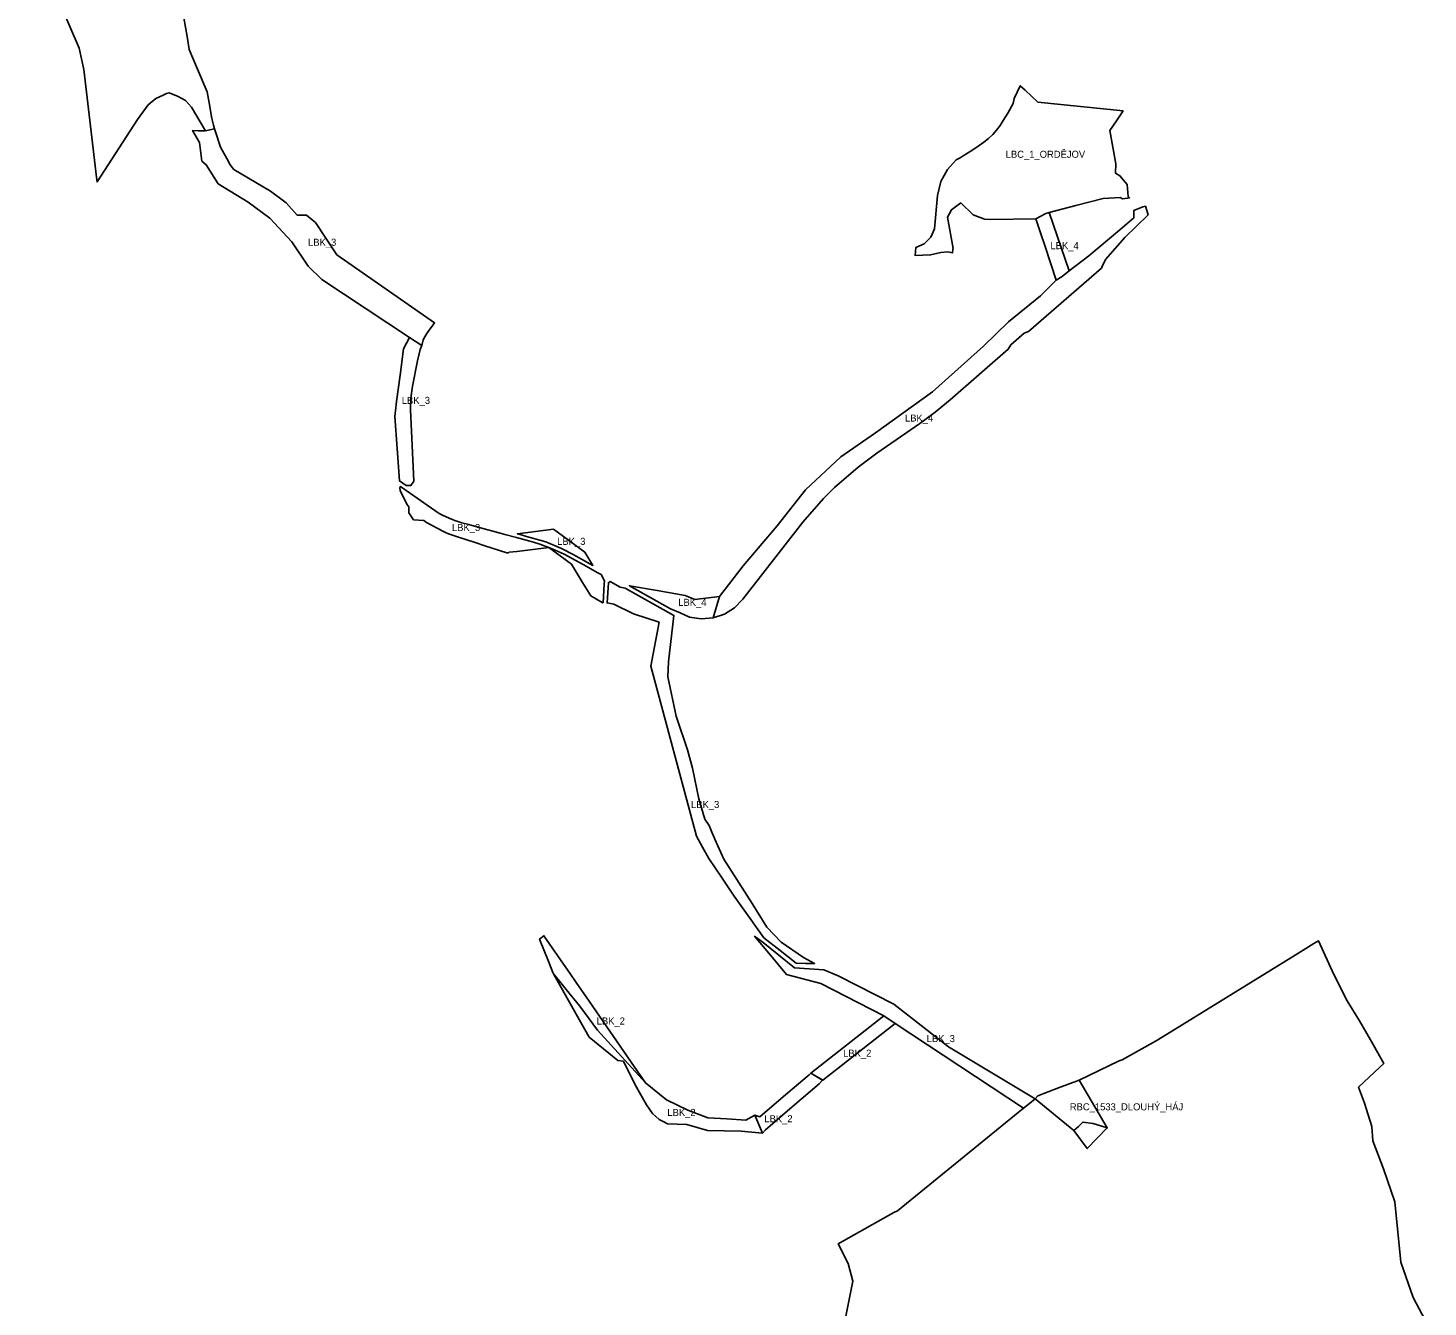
# Model space of a CAD drawing. Extents: x -521939 to -516426, y -1197857 to -1189576.
# Drawn here: x -519448 to -517855, y -1195182 to -1193727 of the extents above; entities that cross this region are included whole.
import ezdxf

# ---------------------------------------------------------------- set-up
doc = ezdxf.new("R2010")
doc.units = 0
for name, color, linetype in [('91250013', 7, 'Continuous'), ('91270013', 7, 'Continuous'), ('91280013', 7, 'Continuous'), ('91280023', 7, 'Continuous')]:
    doc.layers.add(name, color=color, linetype=linetype)

msp = doc.modelspace()

# ---------------------------------------------------------------- linework, layer by layer
at = {"layer": '91250013'}
for points in [[(-517855.27, -1195202.9), (-517872.07, -1195170.61), (-517886.13, -1195130.55), (-517892.85, -1195062.16), (-517905.77, -1195024.59), (-517918.02, -1194992.59), (-517919.16, -1194976.41), (-517927.44, -1194949.61), (-517934.18, -1194931.51), (-517910.02, -1194908.82), (-517905.52, -1194904.59), (-517920.71, -1194877.9), (-517933.13, -1194856.07), (-517947.22, -1194833.42), (-517962.22, -1194803.3), (-517979.82, -1194765.19), (-517984.97, -1194768.36), (-518006.26, -1194781.46), (-518162.69, -1194877.72), (-518167.76, -1194880.84), (-518203.35, -1194900.68), (-518206.51, -1194901.69), (-518252.06, -1194923.56), (-518220.17, -1194977.86), (-518242.88, -1195001.36), (-518257.99, -1194980.81), (-518302.06, -1194944.78)], [(-518302.06, -1194944.78), (-518257.99, -1194980.81), (-518253, -1194976.13), (-518248.01, -1194971.45), (-518236.28, -1194972.79), (-518220.17, -1194977.86), (-518252.06, -1194923.56), (-518275.61, -1194932.46), (-518299.16, -1194941.37), (-518302.06, -1194944.78)], [(-518302.06, -1194944.78), (-518308.71, -1194950.18), (-518315.37, -1194955.58), (-518387.11, -1195013.83), (-518458.85, -1195072.09), (-518462.79, -1195074.28), (-518526.18, -1195109.58), (-518514.93, -1195132.02), (-518509.49, -1195152.1), (-518518.19, -1195195.9)]]:
    msp.add_lwpolyline(points, dxfattribs=at)
at = {"layer": '91270013'}
for points in [[(-519270.68, -1193715.28), (-519266.62, -1193736.71), (-519264.33, -1193751.44), (-519255.98, -1193771.28), (-519244.01, -1193799.73), (-519241.81, -1193812.07), (-519238.75, -1193829.99), (-519237, -1193837.71), (-519235.66, -1193841.81), (-519240.85, -1193842.8), (-519246.03, -1193843.78), (-519261.79, -1193816.98), (-519268.67, -1193809.37), (-519276.88, -1193804.99), (-519287.39, -1193800.73), (-519290.34, -1193801.33), (-519294.27, -1193803.26), (-519302.54, -1193807.3), (-519311.2, -1193814.52), (-519323.09, -1193831.25), (-519369.32, -1193902.04), (-519369.96, -1193896.6), (-519384.42, -1193774.3), (-519389.47, -1193750.04), (-519447.84, -1193614.85)], [(-518301.52, -1193943.97), (-518352.63, -1193944.77), (-518359.82, -1193944.27), (-518372.52, -1193939.49), (-518386.71, -1193925.92), (-518397.26, -1193933.79), (-518401.9, -1193942.24), (-518395.57, -1193977.74), (-518395.64, -1193978.34), (-518396.13, -1193982.66), (-518401.32, -1193981.65), (-518409.46, -1193982.4), (-518421.1, -1193985.13), (-518438.69, -1193985.6), (-518437.85, -1193976.61), (-518428.22, -1193972.32), (-518420.66, -1193964.97), (-518416.55, -1193955.26), (-518413.23, -1193917.44), (-518409.28, -1193901.67), (-518401.76, -1193888.12), (-518391.88, -1193876.83), (-518387.64, -1193874.51), (-518383.89, -1193872.23), (-518374.08, -1193866.27), (-518365.87, -1193860.59), (-518360.35, -1193856.9), (-518355.18, -1193852.77), (-518350.39, -1193848.21), (-518346.01, -1193843.26), (-518342.06, -1193837.96), (-518338.57, -1193832.31), (-518333.17, -1193823.89), (-518327.1, -1193813.04), (-518326.08, -1193807.13), (-518319.09, -1193792.65), (-518313.53, -1193797.88), (-518299.08, -1193811.34), (-518250.59, -1193816.37), (-518202.1, -1193821.4), (-518209.67, -1193832.42), (-518217.23, -1193843.45), (-518210.37, -1193881.64), (-518210.66, -1193892.12), (-518205.81, -1193894.97), (-518197.41, -1193905.18), (-518196.27, -1193918.65), (-518194.69, -1193919.99), (-518195.92, -1193920.22), (-518197.16, -1193920.46), (-518200, -1193920.94), (-518202.84, -1193921.41), (-518205.6, -1193919.97), (-518224.66, -1193920.83), (-518255.82, -1193928.83), (-518286.34, -1193937.02), (-518290.16, -1193938.05), (-518301.52, -1193943.97)]]:
    msp.add_lwpolyline(points, dxfattribs=at)
at = {"layer": '91280013'}
for points in [[(-519013.71, -1194079.07), (-519113.44, -1194013.16), (-519129.07, -1193997.96), (-519147.85, -1193970.15), (-519172.57, -1193943.22), (-519197.38, -1193925.03), (-519231.57, -1193904.08), (-519245.14, -1193882.61), (-519249.93, -1193878.39), (-519252.82, -1193857.23), (-519260.59, -1193843.56), (-519254.04, -1193843.81), (-519247.48, -1193844.06), (-519246.03, -1193843.78), (-519240.85, -1193842.8), (-519235.66, -1193841.81), (-519234.57, -1193845.15), (-519228.9, -1193862.43), (-519221.81, -1193875.3), (-519217.8, -1193882.51), (-519215.12, -1193886.12), (-519213.53, -1193887.89), (-519171.95, -1193912.59), (-519154.26, -1193925.95), (-519141.58, -1193939.77), (-519136.36, -1193939.9), (-519131.15, -1193940.03), (-519124.61, -1193945.28), (-519120.98, -1193948.19), (-519096.71, -1193984.89), (-518985.38, -1194062.49), (-518989.19, -1194067.6), (-518991.71, -1194071.11), (-518994.22, -1194074.61), (-518996.26, -1194078.2), (-518998.31, -1194081.79), (-518999.95, -1194088.17), (-519013.71, -1194079.07)], [(-518301.52, -1193943.97), (-518290.16, -1193938.05), (-518286.34, -1193937.02), (-518263.35, -1194003.2), (-518271.56, -1194009.45), (-518278.37, -1194013.9), (-518290.94, -1193975.36), (-518296.12, -1193959.95), (-518301.52, -1193943.97)], [(-518883.44, -1194304.45), (-518885.16, -1194303.95), (-518891.04, -1194302.25), (-518849.92, -1194297), (-518814.52, -1194323.2), (-518805.31, -1194338.19), (-518827.82, -1194325.64), (-518840.84, -1194318.92), (-518858.91, -1194311.54), (-518883.44, -1194304.45)], [(-518677.75, -1194626.77), (-518673.12, -1194633.99), (-518670.02, -1194641.47), (-518667.28, -1194647.83), (-518666.51, -1194649.62), (-518656.27, -1194672.17), (-518623.89, -1194722.86), (-518607.41, -1194749.43), (-518591.06, -1194766.84), (-518565.58, -1194784.24), (-518553.06, -1194791.06), (-518563.47, -1194790.77), (-518573.88, -1194790.47), (-518592.32, -1194776.2), (-518610.75, -1194761.93), (-518627.58, -1194738.16), (-518644.41, -1194714.39), (-518658.98, -1194692.9), (-518673.54, -1194671.4), (-518680.54, -1194658.74), (-518687.55, -1194646.08), (-518739.33, -1194452.9), (-518729.94, -1194402.91), (-518759.18, -1194393.46), (-518781.58, -1194382.39), (-518789.19, -1194380.84), (-518787.62, -1194357.85), (-518785.49, -1194356.68), (-518774.24, -1194362.95), (-518768.4, -1194363.91), (-518713.15, -1194395.12), (-518719.42, -1194447.81), (-518719.92, -1194464.77), (-518710.33, -1194509.64), (-518697.48, -1194547.94), (-518691.92, -1194568.93), (-518684.82, -1194603.84), (-518677.75, -1194626.77)], [(-518661.16, -1194373.51), (-518668.49, -1194397.81), (-518681.94, -1194398.95), (-518695.28, -1194396.89), (-518705.84, -1194392.3), (-518716.88, -1194387.49), (-518763.75, -1194361.36), (-518732.02, -1194366.81), (-518700.28, -1194372.27), (-518689.13, -1194377.12), (-518661.16, -1194373.51)], [(-518461.21, -1194859.24), (-518474.36, -1194850.51), (-518546.09, -1194813.73), (-518585.19, -1194803.31), (-518603.21, -1194781.62), (-518621.23, -1194759.93), (-518611.71, -1194766.87), (-518575.86, -1194795.7), (-518542.69, -1194798.26), (-518526.37, -1194804.79), (-518463.01, -1194837.27), (-518428.24, -1194864.28), (-518400.82, -1194885.57), (-518302.06, -1194944.78), (-518308.71, -1194950.18), (-518315.37, -1194955.58), (-518461.21, -1194859.24)], [(-518612.46, -1194983.75), (-518624.6, -1194982.61), (-518636.73, -1194981.46), (-518655.75, -1194981.21), (-518674.78, -1194980.96), (-518686.5, -1194977.59), (-518698.22, -1194974.22), (-518709.38, -1194973.72), (-518720.53, -1194973.21), (-518725.18, -1194970.78), (-518729.82, -1194968.36), (-518733.71, -1194964.97), (-518733.71, -1194964.96), (-518737.6, -1194961.57), (-518744.12, -1194951.55), (-518757.12, -1194929), (-518770.47, -1194902.08), (-518776.75, -1194901.38), (-518809.32, -1194874.65), (-518820.69, -1194854.64), (-518850.19, -1194802.69), (-518843.34, -1194811.13), (-518835.53, -1194820.44), (-518820.29, -1194839.32), (-518800.02, -1194866.93), (-518745.52, -1194926.78), (-518721.6, -1194945.89), (-518697.27, -1194957.86), (-518674.42, -1194966.29), (-518652.85, -1194967.73), (-518631.27, -1194969.17), (-518621.14, -1194963.55), (-518612.46, -1194983.75)], [(-518557.27, -1194915.81), (-518474.36, -1194850.51), (-518461.21, -1194859.24), (-518543.85, -1194923.76), (-518557.27, -1194915.81)]]:
    msp.add_lwpolyline(points, dxfattribs=at)
at = {"layer": '91280023'}
for points in [[(-518661.16, -1194373.51), (-518634.33, -1194338.71), (-518595.65, -1194293.01), (-518563.39, -1194252.1), (-518523.23, -1194214.71), (-518483.93, -1194187.46), (-518419.1, -1194140.67), (-518361.02, -1194088.99), (-518332.33, -1194061.21), (-518296.03, -1194031.57), (-518278.37, -1194013.9), (-518271.56, -1194009.45), (-518263.35, -1194003.2), (-518240.91, -1193986.11), (-518205.7, -1193956.46), (-518190.04, -1193942.98), (-518189.98, -1193934.67), (-518179.54, -1193930.3), (-518176.81, -1193929.72), (-518173.64, -1193939.33), (-518200, -1193965.24), (-518222.25, -1193990.41), (-518225.95, -1193998.27), (-518226.78, -1194000.03), (-518309.55, -1194072.16), (-518314.52, -1194073.94), (-518329.88, -1194087.32), (-518332.7, -1194092.34), (-518398.75, -1194149.91), (-518415.71, -1194163.89), (-518433.41, -1194176.9), (-518482.17, -1194210.72), (-518503.56, -1194226.5), (-518530.28, -1194249.78), (-518542.85, -1194262.27), (-518566.27, -1194288.86), (-518634.76, -1194376.7), (-518644.23, -1194386.38), (-518655.68, -1194393.54), (-518668.49, -1194397.81), (-518661.16, -1194373.51)], [(-519013.71, -1194079.07), (-518999.95, -1194088.17), (-519001.62, -1194092.79), (-519004.84, -1194105.44), (-519010.43, -1194134.4), (-519012.2, -1194148.13), (-519012.79, -1194161.44), (-519009.11, -1194242.54), (-519012.22, -1194247.18), (-519017.78, -1194247.27), (-519025.2, -1194242.02), (-519027.95, -1194205.37), (-519030.69, -1194168.71), (-519030.29, -1194165.62), (-519029.89, -1194162.52), (-519028.49, -1194151.72), (-519024.61, -1194121.8), (-519020.73, -1194091.88), (-519013.71, -1194079.07)], [(-519024.49, -1194253.08), (-519017.06, -1194268.42), (-519014.59, -1194271.5), (-519014.52, -1194278.4), (-519009.2, -1194286.28), (-518997.55, -1194287.28), (-518994.7, -1194289.4), (-518975.86, -1194299.17), (-518972.84, -1194300.73), (-518969.65, -1194302.39), (-518959.1, -1194305.82), (-518939.19, -1194312.3), (-518928.2, -1194315.87), (-518903.28, -1194323.98), (-518901.43, -1194323.75), (-518900.67, -1194323.31), (-518891.75, -1194322.51), (-518855.36, -1194317.86), (-518829.53, -1194336.97), (-518816.88, -1194357.57), (-518807.62, -1194372.64), (-518794.51, -1194380.48), (-518793.68, -1194380.64), (-518792.24, -1194359.26), (-518791.99, -1194355.76), (-518795.83, -1194348.62), (-518799.64, -1194346.49), (-518816.36, -1194337.16), (-518838.06, -1194325.4), (-518851.56, -1194319.21), (-518862.69, -1194315.05), (-518865.77, -1194314.1), (-518872.91, -1194311.92), (-518892.05, -1194306.64), (-518905.25, -1194303.03), (-518910.54, -1194301.58), (-518937.1, -1194294.31), (-518946.44, -1194291.75), (-518954.36, -1194289.64), (-518962.17, -1194287.03), (-518966.08, -1194285.71), (-518975.52, -1194281.45), (-518980.26, -1194279.31), (-518993.95, -1194269.72), (-519001.41, -1194264.41), (-519008.87, -1194259.09), (-519017.53, -1194252.96), (-519023.94, -1194248.41), (-519024.71, -1194250.04), (-519024.49, -1194253.08)], [(-518850.19, -1194802.69), (-518850.84, -1194801.06), (-518855.5, -1194789.32), (-518865.86, -1194763.22), (-518860.9, -1194759.36), (-518845.5, -1194781.65), (-518838.55, -1194791.71), (-518831.36, -1194802.11), (-518824.2, -1194812.48), (-518809.54, -1194833.7), (-518758.18, -1194908.03), (-518745.52, -1194926.78), (-518800.02, -1194866.93), (-518820.29, -1194839.32), (-518835.53, -1194820.44), (-518843.34, -1194811.13), (-518850.19, -1194802.69)], [(-518612.46, -1194983.75), (-518621.14, -1194963.55), (-518615.53, -1194965.15), (-518588.48, -1194942.32), (-518561.44, -1194919.5), (-518559.35, -1194917.65), (-518557.27, -1194915.81), (-518543.87, -1194923.75), (-518547.93, -1194927.89), (-518578.49, -1194954.01), (-518609.05, -1194980.13), (-518612.46, -1194983.75)]]:
    msp.add_lwpolyline(points, dxfattribs=at)

# ---------------------------------------------------------------- texts
at = {"layer": '91250013'}
msp.add_text('RBC_1533_DLOUHÝ_HÁJ', height=8, rotation=0, dxfattribs=at).set_placement((-518262.73, -1194957.91))
at = {"layer": '91270013'}
msp.add_text('LBC_1_ORDĚJOV', height=8, rotation=360, dxfattribs=at).set_placement((-518335.65, -1193874.61))
at = {"layer": '91280013'}
for s, rotation, p in [('LBK_3', 360, (-519129.26, -1193974.71)), ('LBK_4', 360, (-518284.74, -1193978.55)), ('LBK_3', 360, (-518845.88, -1194314.81)), ('LBK_4', 0, (-518708.16, -1194384.19)), ('LBK_3', 0, (-518693.59, -1194614.09)), ('LBK_3', 0, (-518425.6, -1194880.33)), ('LBK_2', 360, (-518520.62, -1194896.95)), ('LBK_2', 0, (-518720.54, -1194964.3))]:
    msp.add_text(s, height=8, rotation=rotation, dxfattribs=at).set_placement(p)
at = {"layer": '91280023'}
for s, rotation, p in [('LBK_3', 0, (-519022.65, -1194154.49)), ('LBK_4', 0, (-518450.21, -1194174.6)), ('LBK_3', 360, (-518965.58, -1194299.11)), ('LBK_2', 0, (-518800.95, -1194860.33)), ('LBK_2', 0, (-518610.21, -1194971.46))]:
    msp.add_text(s, height=8, rotation=rotation, dxfattribs=at).set_placement(p)

doc.saveas('drawing.dxf')
